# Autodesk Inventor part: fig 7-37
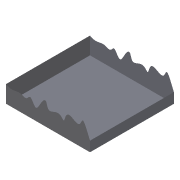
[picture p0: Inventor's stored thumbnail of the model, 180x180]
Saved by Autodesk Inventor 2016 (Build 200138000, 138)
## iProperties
Shininess: 64.0
Length Units: 11269
Angle Units: 11279
Time Units: 11290
Mass Units: 11283
Length Display Precision: 3
Angle Display Precision: 2
Compacted: True
Part Number: fig 7-37
Document SubType Name: Modeling
Created: 2002-12
Designer: deepak
Density: 1 g/cm^3
Material: Generic
Appearance: Default
Density: 0.0
Volumn: 0.0
Area: 0.0
PropertySet Name: Model Information
Control State: 0
Master: False
Checked Out: False
Author: deepak
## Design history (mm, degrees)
sketch "Sketch1"
  geometry: L1 (-32.188, 30.089)-(27.812, 30.089); L2 (27.812, 30.089)-(27.812, -29.911); L3 (27.812, -29.911)-(-32.188, -29.911); L4 (-32.188, -29.911)-(-32.188, 30.089)
  constraints: 8 end point, 2 parallel, 1 horizontal, 1 perpendicular
  dimensions: "d0" = 60 distance of L1.start L1.end; "d1" = 60 distance of L3.end L1.start
extrude "Extrusion1" new body sketch "Sketch1" stored distance "d2" = 20; taper "d3" = 0 deg
sketch "Sketch2"
  geometry: 17 further points
  constraints: 17 other
extrude_surface "ExtrusionSrf1" sketch "Sketch2" dims "d4" = 70, "d5" = 0
split "Split1"
delete_face "Delete Face1"
node "Sketch5"
body "Srf1"
body "Srf2"
